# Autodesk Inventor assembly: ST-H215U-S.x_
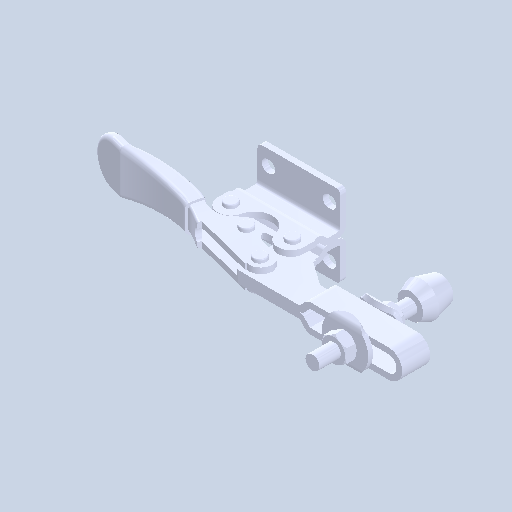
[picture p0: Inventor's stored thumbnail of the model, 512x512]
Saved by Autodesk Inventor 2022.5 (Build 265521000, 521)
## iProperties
Created: 2024-07
Part Number: ST-H215U-S.x_
Document SubType Name: Assembly
Designer: ImaoCorp
Author: ImaoCorp
Sending System: SOLIDWORKS 2022-2022290
MC: AMD64
MC_MODEL: Intel64 Family 6 Model 60 Stepping 3, GenuineIntel
OS: Windows_NT
FRU: Parasolid Version 33.1, build 260,  4-25-2022
FORMAT: text
GUISE: transmit
KEY: FILEST-H215U-S.x_t
DATE: Mon Jul 29 10:02:18 2024
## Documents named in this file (8)
- X:\14_SW2022-Inv2022\07_2024-10新製品(WHS)\OTC_データ\s\st-h215u-s\ST-H215U-S.x_.iam
- X:\14_SW2022-Inv2022\07_2024-10新製品(WHS)\OTC_データ\s\st-h215u-s\ST-H215U-S_01.ipt
- X:\14_SW2022-Inv2022\07_2024-10新製品(WHS)\OTC_データ\s\st-h215u-s\ST-H215U-S_02.ipt
- X:\14_SW2022-Inv2022\07_2024-10新製品(WHS)\OTC_データ\s\st-h215u-s\ST-H215U-S_03.ipt
- X:\14_SW2022-Inv2022\07_2024-10新製品(WHS)\OTC_データ\s\st-h215u-s\ST-H215U-S_04.ipt
- X:\14_SW2022-Inv2022\07_2024-10新製品(WHS)\OTC_データ\s\st-h215u-s\ST-H215U-S_05.ipt
- X:\14_SW2022-Inv2022\07_2024-10新製品(WHS)\OTC_データ\s\st-h215u-s\ST-H215U-S_06.ipt
- X:\14_SW2022-Inv2022\07_2024-10新製品(WHS)\OTC_データ\s\st-h215u-s\ST-H215U-S_07.ipt
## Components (7 placed, 7 different names)
1. ST-H215U-S_01
2. ST-H215U-S_02
3. ST-H215U-S_03
4. ST-H215U-S_04
5. ST-H215U-S_05
6. ST-H215U-S_06
7. ST-H215U-S_07
